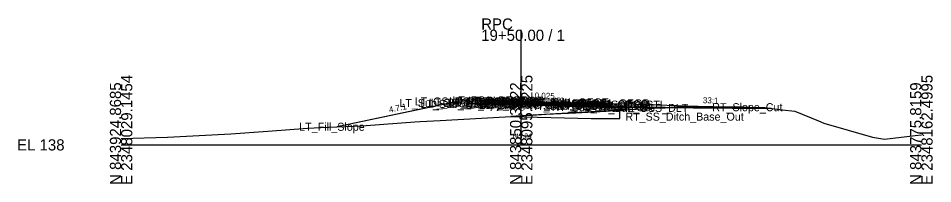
# Model space of a CAD drawing. Extents: x -26 to 203, y -10 to 7538.
# Drawn here: x -25.7 to 202.8, y 5990.3 to 6031.6 of the extents above; entities that cross this region are included whole.
import ezdxf

# ---------------------------------------------------------------- set-up
doc = ezdxf.new("R2010")
doc.units = 0
for name, color, linetype in [('Default', 7, 'Continuous'), ('Exist Cross Section Cell', 7, 'Continuous'), ('Exist XS Center Line Elevation Label', 7, 'Continuous'), ('Exist XS Ground Line', 7, 'Continuous'), ('Prop CMT Pvmt Course 1', 7, 'Continuous'), ('Prop CMT Pvmt Course 2', 7, 'Continuous'), ('Prop CMT Pvmt Course 3', 7, 'Continuous'), ('Prop CMT Pvmt Surface', 7, 'Continuous'), ('Prop CMT Pvmt Surface Shoulder', 7, 'Continuous'), ('Prop CMT Shld Paved Course 1', 7, 'Continuous'), ('Prop CMT Shld Paved Course 2', 7, 'Continuous'), ('Prop CMT Shld Paved Course 3', 7, 'Continuous'), ('Prop CMT Slope Grass', 7, 'Continuous'), ('Prop CMT Subgrade Earthwork', 7, 'Continuous'), ('Prop Road Sect_ Recs - UC (Outline)', 7, 'Continuous'), ('Prop XS Earthwork Shape', 7, 'Continuous'), ('Prop XS SE Text', 7, 'Continuous'), ('Prop XS Side Slope Text', 7, 'Continuous'), ('Scratch_Level_0', 7, 'Continuous')]:
    doc.layers.add(name, color=color, linetype=linetype)

msp = doc.modelspace()

# ---------------------------------------------------------------- linework, layer by layer
at = {"layer": 'Exist Cross Section Cell'}
for p, q in [((100, 6000), (100, 6028.77)), ((0, 6000), (100, 6000)), ((100, 6000), (200, 6000))]:
    msp.add_line(p, q, dxfattribs=at)
at = {"layer": 'Exist XS Ground Line'}
msp.add_lwpolyline([(0, 6001.59), (11.62, 6001.94), (27.44, 6002.72), (36.65, 6003.42), (46.6, 6004.2), (49.88, 6004.34), (60.02, 6004.77), (61.21, 6004.82), (73.43, 6005.72), (74.74, 6005.82), (79.72, 6006.08), (95.99, 6006.98), (100.27, 6007.26), (106.2, 6007.64), (113.69, 6008.01), (121.2, 6008.45), (124.32, 6008.64), (134.52, 6009.22), (137.36, 6009.42), (138.29, 6009.48), (139.84, 6009.57), (140.25, 6009.59), (140.83, 6009.59), (143.15, 6009.58), (144.33, 6009.57), (145.48, 6009.57), (146.52, 6009.56), (147.27, 6009.55), (148.09, 6009.55), (149.88, 6009.53), (151.83, 6009.51), (152.55, 6009.5), (153.19, 6009.49), (155.56, 6009.46), (156.36, 6009.45), (157.12, 6009.43), (159.68, 6009.37), (160.49, 6009.33), (160.96, 6009.31), (164.57, 6008.87), (165.32, 6008.78), (168.36, 6008.43), (174.32, 6005.98), (175.62, 6005.44), (187.78, 6001.94), (190.8, 6001.44), (198.46, 6002.38), (200, 6002.51)], dxfattribs=at)
at = {"layer": 'Prop CMT Pvmt Course 1'}
for p, q in [((100, 6010.92), (96, 6011.02)), ((96, 6011.02), (96, 6010.77)), ((96, 6010.77), (100, 6010.67)), ((100, 6010.67), (100, 6010.92)), ((100, 6010.92), (112, 6010.62)), ((100, 6010.67), (100, 6010.92)), ((100, 6010.67), (100, 6010.79)), ((100, 6010.79), (100, 6010.79)), ((100, 6010.79), (100, 6010.67)), ((100, 6010.67), (100, 6010.79)), ((100, 6010.79), (100, 6010.79)), ((100, 6010.79), (100, 6010.67)), ((100, 6010.67), (100, 6010.67)), ((112, 6010.37), (100, 6010.67)), ((100, 6010.67), (100, 6010.67)), ((112, 6010.62), (112, 6010.37))]:
    msp.add_line(p, q, dxfattribs=at)
at = {"layer": 'Prop CMT Pvmt Course 2'}
for p, q in [((100, 6010.67), (96, 6010.77)), ((96, 6010.77), (96, 6010.44)), ((96, 6010.44), (100, 6010.34)), ((100, 6010.34), (100, 6010.67)), ((100, 6010.34), (100, 6010.67)), ((100, 6010.67), (112, 6010.37)), ((112, 6010.04), (100, 6010.34)), ((112, 6010.37), (112, 6010.04))]:
    msp.add_line(p, q, dxfattribs=at)
at = {"layer": 'Prop CMT Pvmt Course 3'}
for p, q in [((100, 6010.34), (96, 6010.44)), ((96, 6010.44), (96, 6010.1)), ((96, 6010.1), (100, 6010)), ((100, 6010), (100, 6010.34)), ((100, 6010.34), (112, 6010.04)), ((100, 6010), (100, 6010.34)), ((112, 6009.7), (100, 6010)), ((112, 6010.04), (112, 6009.7))]:
    msp.add_line(p, q, dxfattribs=at)
at = {"layer": 'Prop CMT Pvmt Surface'}
for q in [(96, 6011.02), (112, 6010.62)]:
    msp.add_line((100, 6010.92), q, dxfattribs=at)
at = {"layer": 'Prop CMT Pvmt Surface Shoulder'}
for p, q in [((96, 6011.02), (92, 6011.12)), ((112, 6010.62), (122, 6010.37))]:
    msp.add_line(p, q, dxfattribs=at)
at = {"layer": 'Prop CMT Shld Paved Course 1'}
for p, q in [((92, 6011.12), (91.76, 6010.87)), ((91.76, 6010.87), (96, 6010.77)), ((96, 6011.02), (92, 6011.12)), ((96, 6010.77), (96, 6011.02)), ((112, 6010.62), (122, 6010.37)), ((112, 6010.37), (112, 6010.62)), ((122.26, 6010.11), (112, 6010.37)), ((122, 6010.37), (122.26, 6010.11))]:
    msp.add_line(p, q, dxfattribs=at)
at = {"layer": 'Prop CMT Shld Paved Course 2'}
for p, q in [((91.76, 6010.87), (91.43, 6010.55)), ((91.43, 6010.55), (96, 6010.44)), ((96, 6010.77), (91.76, 6010.87)), ((96, 6010.44), (96, 6010.77)), ((112, 6010.37), (122.26, 6010.11)), ((112, 6010.04), (112, 6010.37)), ((122.6, 6009.77), (112, 6010.04)), ((122.26, 6010.11), (122.6, 6009.77))]:
    msp.add_line(p, q, dxfattribs=at)
at = {"layer": 'Prop CMT Shld Paved Course 3'}
for p, q in [((90.93, 6010.56), (90.61, 6010.24)), ((91.43, 6010.55), (90.93, 6010.56)), ((96, 6010.44), (91.43, 6010.55)), ((96, 6010.1), (96, 6010.44)), ((90.61, 6010.24), (96, 6010.1)), ((112, 6010.04), (122.6, 6009.77)), ((112, 6009.7), (112, 6010.04)), ((123.44, 6009.42), (112, 6009.7)), ((122.6, 6009.77), (123.1, 6009.76)), ((123.1, 6009.76), (123.44, 6009.42))]:
    msp.add_line(p, q, dxfattribs=at)
at = {"layer": 'Prop CMT Slope Grass'}
for p, q in [((84, 6010.84), (54, 6004.52)), ((92, 6011.12), (84, 6010.84)), ((122, 6010.37), (126, 6010.23)), ((126, 6010.23), (162.46, 6009.12))]:
    msp.add_line(p, q, dxfattribs=at)
at = {"layer": 'Prop CMT Subgrade Earthwork'}
for p, q in [((90.61, 6010.24), (82.15, 6010.45)), ((96, 6010.1), (90.61, 6010.24)), ((100, 6010), (96, 6010.1)), ((100, 6010), (112, 6009.7)), ((112, 6009.7), (123.44, 6009.42)), ((123.44, 6009.42), (162.46, 6009.12))]:
    msp.add_line(p, q, dxfattribs=at)
at = {"layer": 'Prop Road Sect_ Recs - UC (Outline)'}
msp.add_lwpolyline([(117.44, 6006.57), (124.63, 6006.56), (124.61, 6008.67), (100, 6007.24), (97.38, 6007.07)], close=True, dxfattribs=at)
at = {"layer": 'Prop XS Earthwork Shape'}
for points in [[(54, 6004.52), (60.02, 6004.77), (61.21, 6004.82), (73.43, 6005.72), (74.74, 6005.82), (79.72, 6006.08), (95.99, 6006.98), (100.27, 6007.26), (106.2, 6007.64), (113.69, 6008.01), (121.2, 6008.45), (124.32, 6008.64), (134.52, 6009.22), (135.96, 6009.32), (123.44, 6009.42), (112, 6009.7), (100, 6010), (96, 6010.1), (90.61, 6010.24), (82.15, 6010.45)], [(137.36, 6009.42), (138.29, 6009.48), (139.84, 6009.57), (140.25, 6009.59), (140.83, 6009.59), (143.15, 6009.58), (144.33, 6009.57), (145.48, 6009.57), (146.52, 6009.56), (147.27, 6009.55), (148.09, 6009.55), (148.74, 6009.54), (162.46, 6009.12), (135.96, 6009.32)], [(156.36, 6009.45), (157.12, 6009.43), (159.68, 6009.37), (160.49, 6009.33), (160.96, 6009.31), (162.46, 6009.12), (148.74, 6009.54), (149.88, 6009.53), (151.83, 6009.51), (152.55, 6009.5), (153.19, 6009.49), (155.56, 6009.46)]]:
    msp.add_lwpolyline(points, close=True, dxfattribs=at)

# ---------------------------------------------------------------- texts
at = {"layer": 'Default'}
msp.add_text('-', height=0.0001, dxfattribs=at).set_placement((0, 6000))
at = {"layer": 'Exist Cross Section Cell'}
for s, p in [('RPC', (90, 6028.77)), ('19+50.00 / 1', (90, 6025.97)), ('EL 138', (-26, 5998.6))]:
    msp.add_text(s, height=2.8, dxfattribs=at).set_placement(p)
for s, p in [('E 2348029.1454', (2.8, 5990)), ('E 2348095.8225', (102.8, 5990)), ('E 2348162.4995', (202.8, 5990)), ('N 843924.8685', (0, 5990)), ('N 843850.3422', (100, 5990)), ('N 843775.8159', (200, 5990))]:
    msp.add_text(s, height=2.8, rotation=90, dxfattribs=at).set_placement(p)
at = {"layer": 'Exist XS Center Line Elevation Label'}
msp.add_text('145.24', height=1.2, dxfattribs=at).set_placement((97.55, 6001.64))
at = {"layer": 'Prop XS SE Text'}
msp.add_text('0.025', height=1.5, rotation=358.5679, dxfattribs=at).set_placement((103.34, 6011.58))
at = {"layer": 'Prop XS Side Slope Text'}
for s, rotation, p in [('33:1', 358.2643, (145.37, 6010.42)), ('4.7:1', 11.8976, (67.1, 6008.01))]:
    msp.add_text(s, height=1.5, rotation=rotation, dxfattribs=at).set_placement(p)
at = {"layer": 'Scratch_Level_0'}
for s, p in [('LT_Sub_OSS_DLT', (69.55, 6009.45)), ('LT_GS_OS_CTL', (73.37, 6009.84)), ('LT_Sub_Trench_Out', (74.81, 6009.24)), ('LT_PS3_Shelf_Out', (76.92, 6009.56)), ('LT_PS3_OEOP', (81.67, 6009.55)), ('LT_PS2_OEOP', (81.99, 6009.87)), ('LT_PS1_OEOP', (82.8, 6010.12)), ('LT_Sub_OEOT', (86.08, 6009.1)), ('LT_PV2_OEOT', (86.17, 6009.77)), ('LT_PV3_OEOT', (86.17, 6009.44)), ('LT_PV1_OEOT', (86.74, 6010.02)), ('RT_Sub_OEEOP', (89.17, 6009)), ('LT_Sub_OEEOP', (89.21, 6009)), ('RT_PV2_OEEOP', (89.26, 6009.67)), ('RT_PV3_OEEOP', (89.26, 6009.34)), ('LT_PV2_OEEOP', (89.31, 6009.67)), ('LT_PV3_OEEOP', (89.31, 6009.34)), ('RT_PV1_OEEOP', (89.83, 6009.79)), ('LT_PV1_OEEOP', (89.87, 6009.79)), ('RT_PV2_IEEOP', (89.91, 6009.67)), ('LT_PV2_IEEOP', (89.95, 6009.67)), ('RT_PV1_IEEOP', (90.47, 6009.79)), ('LT_PV1_IEEOP', (90.52, 6009.79)), ('PV2_PGL', (93.91, 6009.67)), ('PV1_PGL', (94.47, 6009.92)), ('RT_Sub_OEOT', (102.03, 6008.7)), ('RT_PV2_OEOT', (102.13, 6009.37)), ('RT_PV3_OEOT', (102.13, 6009.04)), ('RT_PV1_OEOT', (102.69, 6009.62)), ('RT_Sub_Trench_Out', (107.6, 6008.42)), ('RT_PS3_Shelf_Out', (109.04, 6008.76)), ('RT_PS2_OEOP', (112.45, 6009.11)), ('RT_PS1_OEOP', (112.76, 6009.37)), ('RT_PS3_OEOP', (112.79, 6008.77)), ('RT_GS_OS_CTL', (115.32, 6009.05)), ('RT_Slope_Cut', (147.74, 6008.41)), ('RT_Sub_OSS_DLT', (118.27, 6008.23)), ('RT_SS_Ditch_Base_Out', (126.03, 6006.05)), ('LT_Fill_Slope', (44.52, 6003.52))]:
    msp.add_text(s, height=2, dxfattribs=at).set_placement(p)

doc.saveas('drawing.dxf')
